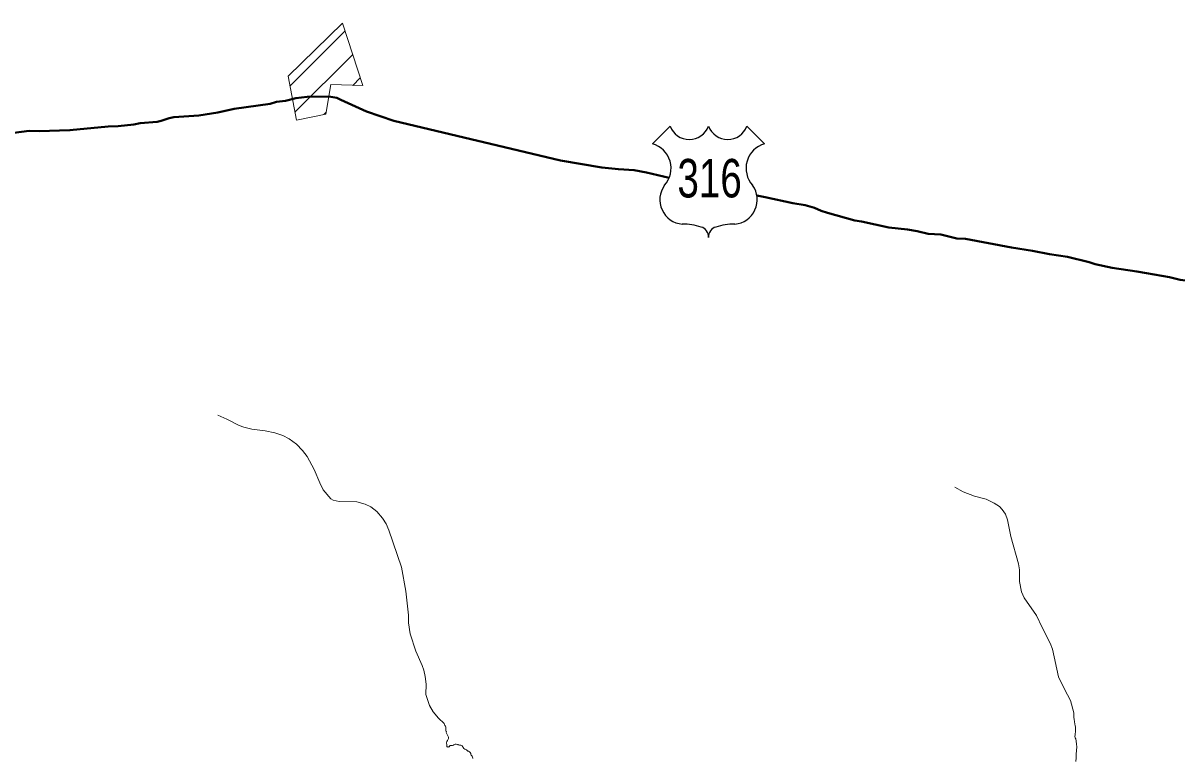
# Model space of a CAD drawing. Extents: x 553962 to 842807, y 8883888 to 9032388.
# Drawn here: x 612051 to 614151, y 8911161 to 8912500 of the extents above; entities that cross this region are included whole.
import ezdxf
from ezdxf.enums import TextEntityAlignment as Align

# ---------------------------------------------------------------- set-up
doc = ezdxf.new("R2010")
doc.units = 0
doc.header["$LTSCALE"] = 20
doc.layers.add('6', color=7, linetype='Continuous', lineweight=13)

msp = doc.modelspace()

# ---------------------------------------------------------------- linework, layer by layer
at = {"layer": '6'}
for p, q in [((612536.57, 8912385.48), (612637.06, 8912485.97)), ((612545.59, 8912337.93), (612650.89, 8912443.23)), ((612651.08, 8912386.85), (612664.72, 8912400.5)), ((612598.08, 8912333.86), (612602.47, 8912338.25))]:
    msp.add_line(p, q, dxfattribs=at)
at = {"layer": '6', "lineweight": 25}
for p, q in [((613196.48, 8912280.48), (613228.47, 8912312.46)), ((613368.33, 8912312.46), (613400.32, 8912280.48))]:
    msp.add_line(p, q, dxfattribs=at)
at = {"layer": '6'}
msp.add_lwpolyline([(612533.17, 8912403.4), (612632.48, 8912500.12), (612669.33, 8912386.27), (612611.16, 8912388.12), (612601.85, 8912334.64), (612548.32, 8912323.53)], close=True, dxfattribs=at)
at = {"layer": '6', "lineweight": 40}
for points in [[(612034.4, 8912300.75), (612062.05, 8912303.96), (612080.24, 8912303.29), (612136.17, 8912305.03), (612205.89, 8912312.14), (612224.01, 8912312.46), (612252.31, 8912315.61), (612263.86, 8912317.74), (612294.81, 8912320.45), (612302.52, 8912322.01), (612316.84, 8912326.84), (612325.21, 8912328.85), (612370.83, 8912331.96), (612405.39, 8912337.71), (612435.17, 8912343.97), (612500.64, 8912353.39), (612512.35, 8912356.61), (612528.33, 8912358.54), (612547.49, 8912363.61), (612568.29, 8912365.96), (612607.23, 8912366.78), (612621.97, 8912364.35), (612629.42, 8912360.3), (612675.78, 8912339.48), (612726.01, 8912322.07), (613028.91, 8912249.9)], [(613028.91, 8912249.9), (613104.31, 8912237.65), (613134.5, 8912234.31), (613163.21, 8912232.24), (613185.33, 8912228.16), (613226.84, 8912218.48)], [(613386.36, 8912186.15), (613401.24, 8912183.61), (613452.08, 8912172.65), (613474.19, 8912168.78), (613491.17, 8912163.86), (613503.68, 8912158.48), (613514.72, 8912154.77), (613564.82, 8912141.01), (613576.62, 8912139.27), (613626.72, 8912128.52), (613660.63, 8912124.51), (613678.29, 8912121.53), (613698.18, 8912116.98), (613721.05, 8912115.6), (613750.54, 8912108.38), (613766.29, 8912107.41), (613849.7, 8912091.93), (613888.06, 8912085.88), (613919.02, 8912079.5), (613951.46, 8912074.85), (613991.23, 8912065.25), (614002.31, 8912061.79), (614033.25, 8912054.89), (614077.81, 8912048.2), (614095.5, 8912045.06)], [(614095.5, 8912045.06), (614137.12, 8912037.66), (614156.64, 8912033.28), (614189.25, 8912028.54), (614215.5, 8912021.67), (614263.47, 8912005.45), (614314.88, 8911983.34), (614359.35, 8911958.14), (614413.54, 8911919.56), (614418.74, 8911918.59), (614421.66, 8911917.15), (614435.25, 8911906.08)]]:
    msp.add_lwpolyline(points, dxfattribs=at)
at = {"layer": '6'}
for points in [[(612405.44, 8911786.91), (612421.94, 8911779.68), (612444.19, 8911767.89), (612452.94, 8911764.74), (612467.01, 8911761.31), (612491.39, 8911758.39), (612508.93, 8911754.94), (612523.97, 8911749.84), (612534.97, 8911743.86), (612548.64, 8911733.83), (612559.67, 8911722.69), (612568.12, 8911711.88), (612580.64, 8911688.16), (612590.89, 8911663.61), (612597.25, 8911651.18), (612610.82, 8911634.7), (612615.13, 8911632.45), (612626.19, 8911629.86), (612658.56, 8911628.85), (612673.5, 8911625.11), (612683.92, 8911620.05), (612694.82, 8911611.3), (612704.98, 8911599.64), (612711.51, 8911589.34), (612716.35, 8911577.62), (612739.5, 8911510.54), (612747.67, 8911466.34), (612752.24, 8911422.9), (612752.64, 8911408.77), (612755.44, 8911388.98), (612765.9, 8911357.31), (612777.38, 8911331.45), (612780.36, 8911322.63), (612782.91, 8911311.58), (612784.37, 8911297.48), (612784.23, 8911278.43), (612790.52, 8911258.56), (612797.41, 8911247.3), (612807.21, 8911235.82), (612817.13, 8911225.86)], [(613746.6, 8911655.6), (613761.81, 8911647.03), (613782.43, 8911639.59), (613803.79, 8911633.7), (613818.29, 8911626.75), (613827.93, 8911620.77), (613832.94, 8911615.19), (613838.72, 8911606.89), (613842.34, 8911596.66), (613848.44, 8911566.07), (613862.41, 8911516.51), (613864.1, 8911505.55), (613864.36, 8911484.41), (613867.7, 8911465.52), (613872.82, 8911454.57), (613895.5, 8911422.26), (613905.6, 8911400.47), (613920.19, 8911371.94), (613924.21, 8911361), (613935.06, 8911310.73), (613946.49, 8911288.09), (613957.43, 8911267.5), (613963.03, 8911245.35)], [(613963.03, 8911245.35), (613963.38, 8911239.49), (613963.51, 8911237.01), (613963.98, 8911233.72), (613964.59, 8911229.09), (613965.93, 8911221.58), (613966.2, 8911220.04), (613966.27, 8911218.77), (613966.44, 8911218.48)], [(612817.13, 8911225.86), (612817.36, 8911225.02), (612817.97, 8911223.94), (612818.59, 8911222.4), (612819.59, 8911220.79), (612820.36, 8911219.48), (612820.59, 8911218.71), (612820.59, 8911217.4), (612820.28, 8911215.94), (612820.21, 8911213.86), (612820.44, 8911213.02), (612821.13, 8911211.56), (612821.28, 8911210.48), (612820.99, 8911209.39)], [(612820.99, 8911209.39), (612821.63, 8911208.33), (612822.37, 8911206.74), (612823.22, 8911204.41), (612824.92, 8911200.91), (612825.34, 8911199.85), (612825.23, 8911198.58), (612824.6, 8911197.1), (612823.11, 8911195.09), (612821.95, 8911193.07), (612821.42, 8911190.85), (612822.27, 8911187.04), (612822.27, 8911184.5), (612822.27, 8911183.48)], [(613965.97, 8911218.48), (613966.23, 8911213.32), (613966.1, 8911210.39), (613965.78, 8911206.96), (613965.34, 8911205.18), (613964.91, 8911202.21), (613965.72, 8911199.58), (613966.61, 8911197.73), (613967.81, 8911188.85), (613968.58, 8911182.61), (613968.13, 8911177.04), (613967.37, 8911169.65), (613967.31, 8911166.24), (613967.69, 8911163.25), (613967.05, 8911156.44)], [(612822.27, 8911183.56), (612823.86, 8911183.1), (612824.79, 8911182.96), (612825.46, 8911183.1), (612826.39, 8911183.63), (612827.52, 8911185.03), (612828.12, 8911185.69), (612828.99, 8911185.96), (612830.52, 8911185.96), (612832.26, 8911185.89), (612834.32, 8911186.56), (612835.19, 8911186.96), (612837.06, 8911188.03), (612838.19, 8911188.23), (612839.26, 8911188.03), (612841.92, 8911187.56), (612843.06, 8911187.16), (612844.26, 8911186.76), (612845.21, 8911186.64)], [(612845.81, 8911186.41), (612847.81, 8911186.22), (612848.75, 8911185.88), (612850.08, 8911185.28), (612851.08, 8911183.42), (612851.75, 8911182.09), (612853.21, 8911180.36), (612854.75, 8911179.42), (612856.61, 8911178.82), (612858.01, 8911178.03), (612859.28, 8911176.76), (612860.21, 8911175.76), (612861.55, 8911175.23), (612863.55, 8911174.36), (612864.88, 8911173.1), (612865.68, 8911171.23), (612866.01, 8911169.77), (612866.57, 8911168.12), (612867.97, 8911166.13), (612868.84, 8911164.73), (612869.37, 8911162.73), (612869.54, 8911162.23)]]:
    msp.add_lwpolyline(points, dxfattribs=at)
at = {"layer": '6', "lineweight": 25}
for centre, radius, start, end in [((613263.43, 8912325.85), 37.44, 200.95927, 339.04073), ((613333.36, 8912325.85), 37.44, 200.95927, 339.04073), ((613184.07, 8912236.1), 46.07, 317.5721, 74.36886), ((613412.73, 8912236.1), 46.07, 105.62774, 222.4279), ((613254.77, 8912179.08), 44.94, 144.73733, 264.65778), ((613342.03, 8912179.08), 44.94, 275.34222, 35.26267), ((613250.38, 8912016.38), 117.95, 72.89371, 89.90057), ((613279.53, 8912111.06), 18.89, 357.69345, 72.92955), ((613317.27, 8912111.06), 18.89, 107.07045, 182.30655), ((613346.42, 8912016.38), 117.95, 90.09943, 107.10629)]:
    msp.add_arc(centre, radius, start, end, dxfattribs=at)

# ---------------------------------------------------------------- texts
at = {"layer": '6', "width": 0.75}
msp.add_text('316', height=70, dxfattribs=at).set_placement((613300.39, 8912182.92), align=Align.CENTER)

doc.saveas('drawing.dxf')
